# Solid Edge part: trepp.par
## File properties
Author: Blackblade
Template: Normal.par
Last saved by: Blackblade
Revision: 2
Application: Solid Edge
Accuracy: 0.990
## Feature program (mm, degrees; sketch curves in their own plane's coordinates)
sketch for "unnamed Protrusion 1" plane through (0, 0, 0) normal (0, -1, 0) x-axis (1, 0, 0)
  line (-25.611, -0.0407) -> (-25.611, -15.0407)
  line (-25.611, -15.0407) -> (-10.611, -15.0407)
  line (-10.611, -15.0407) -> (-10.611, -30.0407)
  line (-10.611, -30.0407) -> (4.389, -30.0407)
  line (4.389, -30.0407) -> (4.389, -45.0407)
  line (4.389, -45.0407) -> (19.389, -45.0407)
  line (19.389, -45.0407) -> (19.389, -54.3682)
  line (19.389, -54.3682) -> (7.0043, -54.3682)
  line (-3.6067, -42.2937) -> (7.0043, -54.3682)
  line (-40.611, -0.0407) -> (-3.6067, -42.2937)
  line (-40.611, -0.0407) -> (-25.611, -0.0407)
extrude "unnamed Protrusion 1" add finite 40 along +normal
fillet "Round_2" radius 5
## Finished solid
Body 1: solid body, 16 faces, 42 edges, 28 vertices.
  Faces by surface: plane 13, cylinder 3
  Edges by curve: line 36, circle 6
Bounding box of the edges (mm): 60.000 x 40.000 x 54.328, from (-40.611, -40, -54.3682) to (19.389, 0, -0.0407).
Cylindrical faces by radius (mm): R5 x3
Planar faces by outward normal: +x 4, +y 1, +z 4, -y 1, -z 1, oblique 2
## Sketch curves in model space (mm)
line (23.8239, 0, -42.2937) -> (23.8239, 0, -40.2937)
line (-3.6067, 0, -42.2937) -> (7.0043, 0, -54.3682)
line (19.389, 0, -54.3682) -> (7.0043, 0, -54.3682)
line (19.389, 0, -45.0407) -> (19.389, 0, -54.3682)
line (4.389, 0, -45.0407) -> (19.389, 0, -45.0407)
line (4.389, 0, -30.0407) -> (4.389, 0, -45.0407)
line (-10.611, 0, -30.0407) -> (4.389, 0, -30.0407)
line (-10.611, 0, -15.0407) -> (-10.611, 0, -30.0407)
line (-25.611, 0, -15.0407) -> (-10.611, 0, -15.0407)
line (-25.611, 0, -0.0407) -> (-25.611, 0, -15.0407)
line (-40.611, 0, -0.0407) -> (-25.611, 0, -0.0407)
line (-40.611, 0, -0.0407) -> (-3.6067, 0, -42.2937)
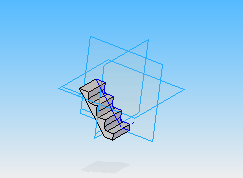
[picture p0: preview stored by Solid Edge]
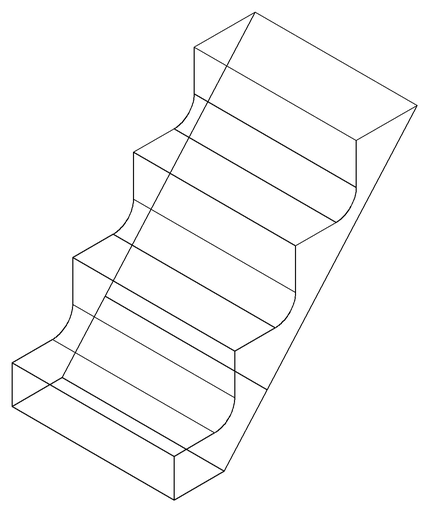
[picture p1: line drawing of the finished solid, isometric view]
